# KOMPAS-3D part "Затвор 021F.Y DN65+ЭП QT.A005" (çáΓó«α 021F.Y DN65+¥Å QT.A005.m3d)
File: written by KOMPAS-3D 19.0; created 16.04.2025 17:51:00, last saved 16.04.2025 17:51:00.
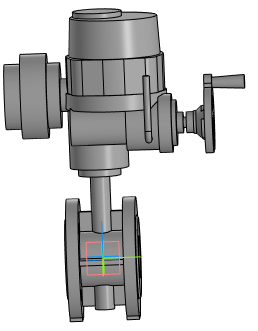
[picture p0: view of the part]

Document properties: Полное имя файла: Затвор 021F.Y DN65+ЭП QT.A005.a3d

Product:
- Part/product: Затвор 021F.Y DN65+ЭП QT.A005
    Масса: 45.962

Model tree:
1. Операция без истории:1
